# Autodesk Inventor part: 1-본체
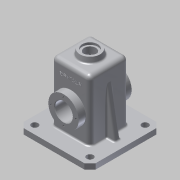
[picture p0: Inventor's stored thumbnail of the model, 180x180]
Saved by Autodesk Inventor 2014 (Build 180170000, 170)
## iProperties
Created: 2016-02
Part Number: 1-본체
Material: 알루미늄 6061
Document SubType Name: Modeling
Designer: 406-05
Density: 2.71 g/cm^3
Appearance: 알루미늄 - 평지
Mass: 920.596 g
Surface Area: 1040.92 cm^2
Volume: 339.703 cm^3
Author: 406-05
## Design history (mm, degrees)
sketch "스케치1"
  geometry: L1 (-35, 35)-(35, 35); L2 (35, 35)-(35, -35); L3 (35, -35)-(-35, -35); L4 (-35, -35)-(-35, 35); L5 (-35, 35)-(35, -35); L6 (35, 35)-(-35, -35); 1 further point
  constraints: 12 end point, 2 midpoint, 2 parallel, 1 horizontal, 1 perpendicular
  dimensions: "d0" = 70 distance of L1.start L1.end; "d1" = 70 distance of L1.end L2.end
extrude "돌출1" new body sketch "스케치1" distance "d2" = 120; taper "d3" = 0 deg
sketch "스케치2"
  geometry: L1 (-65, 65)-(65, 65); L2 (65, 65)-(65, -65); L3 (65, -65)-(-65, -65); L4 (-65, -65)-(-65, 65); L5 (-65, 65)-(65, -65); L6 (65, 65)-(-65, -65); 1 further point
  constraints: 12 end point, 2 midpoint, 2 parallel, 1 horizontal, 1 perpendicular
  dimensions: "d4" = 130 distance of L1.start L1.end; "d5" = 130 distance of L1.end L2.end
extrude "돌출2" join sketch "스케치2" distance "d6" = 10; taper "d7" = 0 deg
chamfer "모따기1" distance "d8" = 10; stored, may be unused: second distance "d9" = 2, angle "d10" = 45 deg
sketch "스케치3"
  geometry: L1 (55, 65)-(-55, 65) reference; L2 (-50, 50)-(50, 50); L3 (50, 50)-(50, -50); L4 (50, -50)-(-50, -50); L5 (-50, -50)-(-50, 50); L6 (-50, 50)-(50, -50); L7 (50, 50)-(-50, -50); 5 further points
  constraints: 12 end point, 4 coincident, 2 midpoint, 2 parallel, 1 horizontal, 1 perpendicular
  dimensions: "d12" = 100 distance of L2.start L2.end; "d13" = 100 distance of L2.end L3.end
hole "구멍1" sketch "스케치3" at (-50, 50), (-50, -50), (50, -50), (50, 50) diameter "d14" = 12; stored, may be unused: countersink angle "d18" = 90 deg, drill point angle "d20" = 118 deg; dims "d15" = 6, "d16" = 4, "d17" = 2, "d19" = 8
fillet "모깎기1" dims "d22" = 8
fillet "모깎기2" dims "d23" = 8
sketch "스케치4"
  geometry: C1 r 27.5 at (0, 55); 1 further point
  constraints: 1 centre point
  dimensions: "d24" = 55 diameter of C1; "d25" = 55 distance of point (0, 0) C1.centre
extrude "돌출3" join sketch "스케치4" stored distance "d26" = 96; taper "d27" = 0 deg
sketch "스케치5"
  geometry: C1 r 20 at (0, 0); 1 further point
  constraints: 1 centre point, 1 coincident
  dimensions: "d28" = 40 diameter of C1
extrude "돌출4" join sketch "스케치5" distance "d29" = 10; taper "d30" = -10 deg; dims "d20" = 118 deg
node "작업 평면1"
sketch "스케치6"
  geometry: L1 (27, 35)-(-27, 35) reference; L2 (-35, 27)-(-35, -27) reference; L3 (35, -27)-(35, 27) reference; L4 (-27, -35)-(27, -35) reference; L5 (27, 30)-(-27, 30); L6 (-30, 27)-(-30, -27); L7 (-27, -30)-(27, -30); L8 (30, -27)-(30, 27); A1 r 8 centre (-27, 27) between (-27, 35) and (-35, 27) reference; A2 r 8 centre (27, 27) between (35, 27) and (27, 35) reference; A3 r 8 centre (27, -27) between (27, -35) and (35, -27) reference; A4 r 8 centre (-27, -27) between (-35, -27) and (-27, -35) reference; A5 r 3 centre (27, 27) between (30, 27) and (27, 30); A6 r 3 centre (-27, 27) between (-27, 30) and (-30, 27); A7 r 3 centre (-27, -27) between (-30, -27) and (-27, -30); A8 r 3 centre (27, -27) between (27, -30) and (30, -27); 1 further point
  constraints: 8 end point, 8 point on circle, 4 centre point, 7 other
  dimensions: "d32" = 5 distance between parallel lines of L3 L8
extrude "돌출5" cut sketch "스케치6" stored distance "d33" = 10; taper "d34" = 0 deg
sketch "스케치8"
  geometry: C1 r 27.5 at (27, 60); 1 further point
  constraints: 1 centre point
  dimensions: "d47" = 55 diameter of C1; "d48" = 55 distance of point (27, 115) C1.centre
extrude "돌출7" join sketch "스케치8" distance "d49" = 7; taper "d50" = -45 deg
hole "구멍3" diameter "d53" = 32; stored, may be unused: countersink angle "d57" = 90 deg, drill point angle "d59" = 118 deg; dims "d51" = 10, "d52" = 10, "d54" = 6, "d55" = 4, "d56" = 2, "d58" = 8
hole "구멍4" diameter "d62" = 21; stored, may be unused: countersink angle "d66" = 90 deg, drill point angle "d68" = 118 deg; dims "d60" = 10, "d61" = 10, "d63" = 6, "d64" = 28, "d65" = 4, "d67" = 8
sketch "스케치9"
  geometry: C1 r 16 at (0, 0) reference; 2 further points
  constraints: 1 vertical alignment
  dimensions: "d69" = 22.5 distance of C1.centre point (0, 22.5)
hole "구멍5" sketch "스케치9" at (0, 22.5) diameter "d70" = 3.242; stored, may be unused: countersink angle "d74" = 90 deg, drill point angle "d76" = 118 deg; dims "d71" = 8, "d72" = 28, "d73" = 4, "d75" = 10
fillet "모깎기3" dims "d80" = 3
sketch "스케치10"
  geometry: L1 (50, 10)-(35, 95.069); L2 (35, 112)-(35, 10) reference; L3 (44, 10)-(56, 10) reference; L4 (55, 10)-(65, 10) reference; L5 (65, 10)-(65, 0) reference; 1 further point
  constraints: 2 end point, 2 point on line
  dimensions: "d81" = 15 distance from line of L5 L1.start; "d100" = 10 deg angle of L5 L1
feature "리브1" sketch "스케치10" dims "d82" = 1, "d83" = 10, "d84" = 0, "d85" = 0, "d86" = 1, "d87" = 1
sketch "스케치11"
  geometry: L1 (8.763, 18)-(45.237, 18) reference; A1 r 27.5 centre (27, -57) between (54, -51.78) and (0, -51.78) reference; 2 further points
  constraints: 1 vertical alignment, 1 other
  dimensions: "d88" = 30 distance from line of point (27, -12) L1
feature "엠보싱1" sketch "스케치11" dims "d0" = 70, "d1" = 70, "d89" = 0.5, "d90" = 0
fillet "모깎기4" dims "d91" = 0.5
chamfer "모따기2" distance "d92" = 1; stored, may be unused: second distance "d93" = 2, angle "d94" = 45 deg
fillet "모깎기5" dims "d95" = 3
fillet "모깎기6" dims "d96" = 3
fillet "모깎기7" dims "d97" = 3
fillet "모깎기8" dims "d98" = 0.5
fillet "모깎기9" dims "d99" = 3
node "솔리드1"
mirror "대칭2"
pattern_circular "원형 패턴1" dims angle "d78" = 360 deg
mirror "대칭3"
mirror "대칭4"
other parameters: "d31" = -5
